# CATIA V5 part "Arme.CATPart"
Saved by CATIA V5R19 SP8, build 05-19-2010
Part number: Arme
Bounding box of the stored display mesh (mm): x -51.144 to 50.176, y -1292.323 to 149.172, z 1303.685 to 1514.727
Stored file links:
  G:\EU_thinkMotion\CFAO_2010\MMS_groupe2\MMS_groupe2\OK\nrosalie\nrosalie_cfao_support_d_arme_legere_final\Arme.CATPart
  G:\EU_thinkMotion\CFAO_2010\MMS_groupe2\MMS_groupe2\OK\nrosalie\nrosalie_cfao_support_d_arme_legere_final\nrosalie_Support_d_arme_legere.CATProduct
  G:\EU_thinkMotion\CFAO_2010\MMS_groupe2\MMS_groupe2\OK\nrosalie\nrosalie_cfao_support_d_arme_legere_final\Squelette_Systeme_de_visee.CATPart
  C:\Espace travail\Cours 2A MMS\CFAO\Projet CFAO\Modele CAO\Version_finale_sans_siege\Symmetry of Piece_de_support.CATPart
  C:\Espace travail\Cours 2A MMS\CFAO\Projet CFAO\Modele CAO\Version_finale_sans_siege\Symmetry of Bras.CATPart
  G:\EU_thinkMotion\CFAO_2010\MMS_groupe2\MMS_groupe2\OK\nrosalie\nrosalie_cfao_support_d_arme_legere_final\Squelette_bras.CATPart
  G:\EU_thinkMotion\CFAO_2010\MMS_groupe2\MMS_groupe2\OK\nrosalie\nrosalie_cfao_support_d_arme_legere_final\Axe_positionnement_arme.CATPart
  G:\EU_thinkMotion\CFAO_2010\MMS_groupe2\MMS_groupe2\OK\nrosalie\nrosalie_cfao_support_d_arme_legere_final\Bras.CATPart
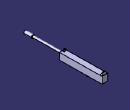
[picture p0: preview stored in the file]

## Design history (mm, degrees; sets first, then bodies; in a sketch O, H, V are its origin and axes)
Set1
  Sketch1 on Plane1, origin (0.0153, 218.5027, 0.1335), H (-1, 0.0012, 0), V (0, -0.0144, 0.9999)
    line L1 (-49.878, 1468.559) -> (50.122, 1468.5604)
    line L2 (50.122, 1468.5604) -> (50.1237, 1348.5604)
    line L3 (50.1237, 1348.5604) -> (-49.8763, 1348.559)
    line L4 (-49.8763, 1348.559) -> (-49.878, 1468.559)
    reference intersected line E1 through (-0.0014, 1348.5597) direction (-1, 0) from Plane2
    reference intersected line E2 through (50.1428, 0) direction (0, -1) from Plane3
    reference intersected line E3 through (-49.8572, 0) direction (0, -1) from Plane4
    reference intersected line E4 through (-0.0014, 1498.5597) direction (-1, 0) from Plane5
    distance L1 E4 = 30
    coincidence: L3 E1, L2 E2, L4 E3
Set2
  Plane1: linked copy from another document
  Plane2 "Plan_limite_inferieur_de_l_arme": linked copy from another document
  Plane3 to Plane6: linked copy from another document
  Point1: linked copy from another document
  Point2: linked copy from another document
  Line1: linked copy from another document
  Point3: linked copy from another document
  Point4: linked copy from another document
  DatumCurve1: linked copy from another document
  Plane7: linked copy from another document
  DatumSurface1: linked copy from another document
Body1 (main body)
  Pad1: profile Sketch1, direction (0.0012, 0.9999, 0.0144), up to Plane6, offset 20, opposite side up to Plane1, offset -50
  Sketch2 on end face of Pad1, origin (0.0152, -601.5828, 0.1329), H (1, -0.0012, 0), V (0, -0.0144, 0.9999)
    circle A1 centre (-1.1425, 1421.7639) radius 25
    point P1 (-1.1425, 1421.7639)
    reference projected line E1 (48.858, 1456.7632) -> (-51.142, 1456.7647) from edge [face of Pad1 from Sketch1.L1 | end face of Pad1]
    reference projected line E2 (-51.1437, 1336.7647) -> (-51.142, 1456.7647) from edge [end face of Pad1 | face of Pad1 from Sketch1.L2]
    reference projected line E3 (48.8563, 1336.7632) -> (48.858, 1456.7632) from edge [face of Pad1 from Sketch1.L4 | end face of Pad1]
    radius A1 = 25
    distance A1 E1 = 10
    equidistance: E2 E3 P1
  Pad2: profile Sketch2, direction (-0.0012, -0.9999, -0.0144), length 20
  Sketch3 on end face of Pad2, origin (0.0152, -621.5849, 0.1329), H (1, -0.0012, 0), V (0, -0.0144, 0.9999)
    circle A1 centre (-1.1674, 1421.4762) radius 20
    reference projected circle E1 centre (-1.1674, 1421.4762) radius 25 from edge [face of Pad2 from Sketch2.A1 | end face of Pad2]
    reference projected circle E2 centre (-1.1674, 1421.4762) radius 25 from edge [face of Pad2 from Sketch2.A1 | end face of Pad2]
    distance A1 E2 = 5
    concentricity: A1 E1
  Pad3: profile Sketch3, direction (-0.0012, -0.9999, -0.0144), length 500
  Sketch4 on end face of Pad3, origin (0.0152, -1121.637, 0.1326), H (1, -0.0012, 0), V (0, -0.0144, 0.9999)
    circle A1 centre (-1.7893, 1414.2837) radius 30
    reference projected circle E1 centre (-1.7893, 1414.2837) radius 20 from edge [face of Pad3 from Sketch3.A1 | end face of Pad3]
    radius A1 = 30
    concentricity: A1 E1
  Pad4: profile Sketch4, direction (-0.0012, -0.9999, -0.0144), length 150
  Fillet1: radius 5, on edge [start face of Pad4 | face of Pad4 from Sketch4.A1]
  Fillet2: radius 5, on edge [face of Pad4 from Sketch4.A1 | end face of Pad4]
  Sketch5 on end face of Pad4, origin (0.0152, -1271.6526, 0.1325), H (1, -0.0012, 0), V (0, -0.0144, 0.9999)
    circle A1 centre (-1.9759, 1412.1259) radius 12.5
    reference projected circle E1 centre (-1.9759, 1412.1259) radius 25 from edge [face of Fillet2 | end face of Pad4]
    radius A1 = 12.5
    concentricity: A1 E1
  Pocket1: profile Sketch5, direction (0.0012, 0.9999, 0.0144), length 700
  Sketch6 on yz-plane, origin (0, 0, 0), H (0, 1, 0), V (0, 0, 1)
    circle A1 centre (-150.4272, 1313.5223) radius 5
    point P1 (-150.4272, 1313.5223)
    arc A2 centre (-150.4272, 1313.5223) radius 10 from (-159.9601, 1310.5015) to (-140.8944, 1310.5015) ccw
    point P2 (-150.4272, 1313.5223)
    line L1 (-170.334, 1343.2389) -> (-159.9601, 1310.5015)
    point P4 (-170.334, 1343.2389)
    line L2 (-140.8944, 1310.5015) -> (-130.3382, 1343.8143)
    point P6 (-130.3382, 1343.8143)
    line L3 (-170.334, 1343.2389) -> (-130.3382, 1343.8143)
    point P7 (-170.334, 1343.2389)
    reference projected line E1 (-601.3453, 1337.0385) -> (48.5875, 1346.3883) from edge [face of Pad1 from Sketch1.L3 | face of Pad1 from Sketch1.L4]
    axis line L4 (-150.4272, 1343.6292) -> (-150.4272, 1299.3242)
    reference projected point E2 (-150.4272, 1313.5223) from Point4
    reference projected point E3 (-150.4272, 1313.5223) from Point4
    reference projected point E4 (-150.4272, 1313.5223) from Point4
    distance A1 A2 = 5
    radius A1 = 5
    distance P6 P4 = 40
    coincidence: L3 E1, L4 E2, P4 P7, E3 P1, P2 E4
    tangency: L2 A2, A2 L1
    vertical: L4 V
    symmetry: L1 L2 L4
  Pad5: profile Sketch6, direction (1, 0, 0), length 25, mirrored extent
  Sketch7 on yz-plane, origin (0, 0, 0), H (0, -1, 0), V (0, 0, 1)
    circle A1 centre (582.9716, 1462.3185) radius 2.5
    point P1 (582.9716, 1462.3185)
    axis line L1 (582.9716, 1597.9632) -> (582.9716, 1393.4092)
    reference projected point E1 (582.9716, 1487.3185) from Point2
    reference projected point E2 (582.9716, 1487.3185) from Point2
    radius A1 = 2.5
    distance P1 E2 = 25
    vertical: L1 V
    coincidence: L1 E1, P1 L1
  Shaft1: profile Sketch7, axis Line1, angle 360
  Sketch8 on yz-plane, origin (0, 0, 0), H (0, -1, 0), V (0, 0, 1)
    axis line L1 (582.9716, 1536.4241) -> (582.9716, 1444.4797)
    reference projected point E1 (582.9716, 1487.3185) from Point2
    point P3 (582.9716, 1511.6259)
    line L2 (582.9716, 1462.3159) -> (585.4713, 1462.2799)
    line L3 (585.4713, 1462.2799) -> (582.9716, 1479.8652)
    point P6 (582.9716, 1479.8652)
    line L4 (582.9716, 1479.8652) -> (582.9716, 1462.3159)
    reference projected line E2 (601.3454, 1487.0541) -> (-198.5718, 1498.5616) from Line1
    length L2 = 2.5
    distance L2 E2 = 25
    vertical: L1 V, L4 V
    coincidence: L1 E1, P3 L1, P6 L1
  Shaft2: profile Sketch8, axis Sketch8.L1, angle 360
  CircPattern1: of Shaft2, instances 4, angular step 90, axis from Line1
  Sketch9 on face of Pad1 from Sketch1.L1, origin (0.0002, -1.4074, 1465.6816), H (1, 0, 0), V (0, 0.9999, 0.0144)
    line L1 (-6.0945, -579.1928) -> (3.9055, -579.1928)
    line L2 (3.9055, -579.1928) -> (3.9055, -583.1928)
    line L3 (3.9055, -583.1928) -> (-6.0945, -583.1928)
    line L4 (-6.0945, -583.1928) -> (-6.0945, -579.1928)
    reference projected point E1 (-1.0945, -581.1928) from Point2
    reference projected point E2 (-1.0945, -581.1928) from Point2
    length L1 = 10
    length L2 = 4
    horizontal: L1 H, L3 H
    vertical: L2 V, L4 V
    equidistance: L3 L1 E1, L4 L2 E2
  Pad6: profile Sketch9, direction (0, -0.0144, 0.9999), up to face of Shaft1 from Sketch7.A1
  Sketch10 on face of Pad1 from Sketch1.L2, origin (-50.3993, 0.0002, 0), H (-0.0012, -1, 0), V (0, 0, 1)
    line L1 (-141.9673, 1467.7443) -> (-132.0164, 1512.8186)
    line L2 (-132.0164, 1512.8186) -> (-122.0164, 1512.8186)
    line L3 (-122.0164, 1512.8186) -> (-111.9704, 1467.3128)
    line L4 (-141.9673, 1467.7443) -> (-111.9704, 1467.3128)
    reference projected line E1 (601.3454, 1457.0511) -> (-148.577, 1467.8394) from edge [face of Pad1 from Sketch1.L1 | face of Pad1 from Sketch1.L2]
    axis line L5 (-127.0164, 1451.7825) -> (-127.0164, 1338.4005)
    reference projected point E2 (-127.0164, 1497.5323) from Point3
    reference projected point E3 (-146.7986, 1512.8186) from vertex [element of Sketch11 | element of Sketch11]
    length L2 = 10
    length L4 = 30
    horizontal: L2 H
    coincidence: L4 E1, E2 L5, L2 E3
    vertical: L5 V
    symmetry: L1 L3 L5
  Sketch11 on start face of Pad1, origin (0.0153, 168.4974, 0.1335), H (-1, 0.0012, 0), V (0, -0.0144, 0.9999)
    line L1 (-50.1853, 1467.8398) -> (50.1842, 1467.8412)
    point P2 (50.1842, 1467.8412)
    line L2 (50.1842, 1467.8412) -> (14.9998, 1512.8407)
    line L3 (14.9998, 1512.8407) -> (5, 1512.8405)
    line L4 (5, 1512.8405) -> (5, 1502.8405)
    line L5 (5, 1502.8405) -> (-5, 1502.8405)
    line L6 (-5, 1502.8405) -> (-5, 1512.8404)
    point P7 (-5, 1512.8404)
    line L7 (-5, 1512.8404) -> (-15, 1512.8404)
    line L8 (-15, 1512.8404) -> (-50.1853, 1467.8398)
    axis line L9 (0, 1771.0951) -> (0, 1653.1752)
    point P9 (0, 1771.0951)
    reference projected line E1 (-50.0014, 1467.8398) -> (49.9986, 1467.8412) from edge [start face of Pad1 | face of Pad1 from Sketch1.L1]
    reference projected line E2 (50.1823, 1600) -> (50.1813, 1670) from edge [face of Pad1 from Sketch1.L2 | start face of Pad1]
    reference projected point E3 (0.1838, 1497.8405) from Line1
    length L7 = 10
    length L5 = 10
    distance L3 L1 = 45
    distance L5 E3 = 5
    horizontal: L5 H, L7 H
    coincidence: P7 L3, P9 V, L1 E1, P2 E2
    vertical: L9 V, L4 V
    symmetry: L2 L8 L9, L4 L6 L9
  SolidCombine1: FirstComponentProfile Sketch10, FirstComponentDirection Sketch10, SecondComponentProfile Sketch11, SecondComponentDirection Sketch11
